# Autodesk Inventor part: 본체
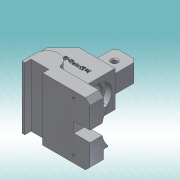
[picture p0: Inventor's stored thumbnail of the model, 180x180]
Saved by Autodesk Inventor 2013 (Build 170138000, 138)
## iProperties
Created: 2016-11
Part Number: 본체
Material: 알루미늄 6061
Document SubType Name: Modeling
Designer: dgall
Mass: 456.053 g
Surface Area: 313.578 cm^2
Volume: 168.285 cm^3
Density: 2.71 g/cm^3
Author: dgall
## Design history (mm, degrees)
sketch "스케치4"
  geometry: L1 (0, 0)-(58, 0); L2 (58, 0)-(58, 48); L3 (58, 48)-(0, 48); L4 (0, 48)-(0, 0)
  constraints: 8 end point, 2 parallel, 1 horizontal, 1 perpendicular
  dimensions: "d13" = 58 distance of L2.end L3.end; "d16" = 48 distance of L3.end L1.start
extrude "돌출3" new body sketch "스케치4" distance "d17" = 40; taper "d18" = 0 deg
node "작업 평면1"
sketch "스케치5"
  geometry: L1 (58, 48)-(18, 48) reference; L2 (58, 3)-(58, 48) reference; 2 further points
  constraints: 1 other
  dimensions: "d33" = 18 distance from line of L1 point (33, 30); "d105" = 25 distance from line of L2 point (33, 30)
sketch "스케치6"
  geometry: L1 (14, 15)-(90, 15); L2 (90, 15)-(90, -55); L3 (90, -55)-(14, -55); L4 (14, -55)-(14, 15); L5 (58, 0)-(0, 0) reference; L6 (58, -40)-(0, -40) reference; L7 (58, 0)-(58, -40) reference; L8 (58, -20)-(68.785, -20); L9 (0, 0)-(0, -40) reference
  constraints: 10 end point, 2 parallel, 2 perpendicular, 1 horizontal, 1 midpoint, 1 other
  dimensions: "d22" = 70 distance of L1.end L2.end; "d24" = 76 distance of L2.end L3.end; "d106" = 90 distance between parallel lines of L2 L9
extrude "돌출4" join sketch "스케치6" distance "d25" = 15; taper "d26" = 0 deg
sketch "스케치7"
  geometry: L1 (0, 0)-(14, 0) reference; L2 (0, 30)-(18, 48); L3 (18, 48)-(0, 48); L4 (0, 48)-(0, 30)
  constraints: 6 end point, 1 parallel, 1 perpendicular
  dimensions: "d28" = 18 distance of L2.end L3.end
extrude "돌출5" cut sketch "스케치7" stored distance "d29" = 15; taper "d30" = 0 deg
extrude "돌출6" join sketch "스케치5" distance "d31" = 0.5; taper "d32" = 0 deg
sketch "스케치8"
  geometry: L1 (-40, 40)-(-40, 0) reference; L2 (0, 0)-(-40, 0) reference; L3 (0, 40)-(0, 0) reference; L4 (0, 40)-(-40, 40) reference; L5 (0, 20)-(-68.106, 20); L6 (-5, 30)-(-30, 30); L7 (-30, 30)-(-30, 10); L8 (-30, 10)-(-5, 10); L9 (-5, 10)-(-5, 30); L10 (-58, 0)-(-58, 40) reference
  constraints: 10 end point, 3 parallel, 1 horizontal, 1 midpoint, 1 perpendicular, 1 other
  dimensions: "d36" = 20 distance of L6.end L7.end; "d38" = 25 distance of L6.start L6.end; "d40" = 53 distance between parallel lines of L9 L10
extrude "돌출7" join sketch "스케치8" distance "d41" = 30; taper "d42" = 0 deg
chamfer "모따기1" distance "d43" = 4; stored, may be unused: second distance "d44" = 2, angle "d45" = 45 deg
sketch "스케치9"
  geometry: L1 (90, -55)-(90, 15) reference; L2 (90, 0)-(90, -40); L3 (90, 0)-(0, 0); L4 (0, 0)-(0, -40); L5 (0, -40)-(90, -40)
  constraints: 8 end point, 2 perpendicular, 1 parallel, 1 point on line
  dimensions: "d46" = 40 distance of L2.start L2.end
extrude "돌출8" join sketch "스케치9" distance "d48" = 5; taper "d49" = 0 deg
chamfer "모따기2" distance "d50" = 4; stored, may be unused: second distance "d51" = 2, angle "d52" = 45 deg
sketch "스케치10"
  geometry: L1 (76, 0)-(0, 0) reference; L2 (0, 15)-(76, 15) reference; L3 (0, 0)-(0, 15) reference; L4 (3, 0)-(23, 0); L5 (23, 0)-(23, 7); L6 (23, 7)-(3, 7); L7 (3, 7)-(3, 0); 2 further points
  constraints: 8 end point, 2 parallel, 2 point on line, 1 horizontal, 1 horizontal alignment, 1 perpendicular, 2 other
  dimensions: "d53" = 3 distance between parallel lines of L3 L7; "d54" = 20 distance between parallel lines of L5 L7; "d55" = 7 distance between parallel lines of L1 L6
extrude "돌출9" join sketch "스케치10" distance "d56" = 70; taper "d57" = 0 deg
extrude "돌출10" cut sketch "스케치10" distance "d58" = 70; taper "d59" = 0 deg
sketch "스케치11"
  geometry: L1 (40, -40)-(40, 0) reference; L2 (40, 0)-(0, 0) reference; L3 (0, -40)-(0, 0) reference; L4 (0, -40)-(40, -40) reference; L5 (40, -48)-(0, -48) reference; C1 r 10 at (20, -18); C2 r 14.5 at (20, -18)
  constraints: 2 centre point, 1 coincident
  dimensions: "d60" = 29 diameter of C2; "d62" = 20 diameter of C1; "d130" = 30 distance from line of L5 C1.centre
extrude "돌출11" cut sketch "스케치11" distance "d63" = 70; taper "d64" = 0 deg
extrude "돌출12" cut sketch "스케치11" distance "d65" = 7; taper "d66" = 0 deg
sketch "스케치12"
  geometry: L1 (4, 30)-(21, 30) reference; L2 (0, 0)-(0, 26) reference; L3 (25, 0)-(25, 26) reference; L4 (62, -60)-(9, -60) reference; 2 further points
  dimensions: "d67" = 12.5 distance from line of L2 point (12.5, 17); "d68" = 77 distance from line of point (12.5, 17) L4
hole "구멍1" sketch "스케치12" at (12.5, 17) diameter "d69" = 6; stored, may be unused: countersink angle "d73" = 90 deg, drill point angle "d75" = 118 deg; dims "d70" = 6, "d71" = 4, "d72" = 2, "d74" = 8
chamfer "모따기3" distance "d76" = 1; stored, may be unused: second distance "d77" = 2, angle "d78" = 45 deg
chamfer "모따기4" distance "d79" = 1; stored, may be unused: second distance "d80" = 2, angle "d81" = 45 deg
sketch "스케치13"
  geometry: L1 (70, 0)-(0, 0) reference; L2 (70, 0)-(70, 15) reference; L3 (55, 15)-(70, 15) reference; L4 (55, 15)-(55, 20) reference; L5 (15, 20)-(55, 20) reference; L6 (15, 15)-(15, 20) reference; L7 (0, 15)-(15, 15) reference; L8 (0, 0)-(0, 15) reference; C1 r 14.5 at (35, 42) reference; C2 r 29 at (35, 42); 1 further point
  constraints: 1 centre point, 1 coincident
  dimensions: "d82" = 58 diameter of C2
extrude "돌출13" cut sketch "스케치13" distance "d84" = 18; taper "d85" = 0 deg
sketch "스케치14"
  geometry: L1 (15, 15)-(15, 20) reference; L2 (0, 15)-(15, 15) reference; L3 (0, 0)-(0, 15) reference; L4 (70, 0)-(0, 0) reference; L5 (70, 0)-(70, 15) reference; L6 (55, 15)-(70, 15) reference; L7 (55, 15)-(55, 20) reference; L8 (29, 0)-(41, 0); L9 (41, 0)-(41, 15.102); L10 (41, 15.102)-(29, 15.102); L11 (29, 15.102)-(29, 0); L12 (35, 13)-(35, -3.878); L13 (15, 20)-(16.106, 20) reference; L14 (53.894, 20)-(55, 20) reference; A1 r 29 centre (35, 42) between (16.106, 20) and (53.894, 20) reference; 1 further point
  constraints: 10 end point, 3 parallel, 1 horizontal, 1 perpendicular, 1 point on circle, 1 point on line, 1 other
  dimensions: "d87" = 12 distance between parallel lines of L9 L11
extrude "돌출14" cut sketch "스케치14" distance "d89" = 18; taper "d90" = 0 deg
sketch "스케치15"
  geometry: L1 (90, 0)-(90, 15) reference; L2 (40, 15)-(40, 0) reference; L3 (90, 0)-(40, 0) reference; L4 (90, 0)-(90, 15) reference; L5 (90, 15)-(40, 15) reference; L6 (40, -40)-(40, -55) reference; L7 (40, -55)-(90, -55) reference; L8 (90, -55)-(90, -40) reference; L9 (90, -40)-(40, -40) reference; 3 further points
  dimensions: "d91" = 18 distance from line of L8 point (72, -47.5); "d92" = 18 distance from line of L1 point (72, 7.5); "d114" = 55 distance of point (72, -47.5) point (72, 7.5)
  node "투영된 루프4"
  node "투영된 루프5"
chamfer "모따기5" distance "d100" = 5; stored, may be unused: second distance "d101" = 2, angle "d102" = 45 deg
fillet "모깎기1" dims "d103" = 3
fillet "모깎기2" dims "d104" = 3
hole "구멍4" sketch "스케치15" diameter "d123" = 3.242; stored, may be unused: countersink angle "d127" = 90 deg, drill point angle "d129" = 118 deg; dims "d124" = 6, "d125" = 4, "d126" = 2, "d128" = 8
node "솔리드3"
node "투영된 루프1"
node "투영된 루프2"
node "투영된 루프3"
